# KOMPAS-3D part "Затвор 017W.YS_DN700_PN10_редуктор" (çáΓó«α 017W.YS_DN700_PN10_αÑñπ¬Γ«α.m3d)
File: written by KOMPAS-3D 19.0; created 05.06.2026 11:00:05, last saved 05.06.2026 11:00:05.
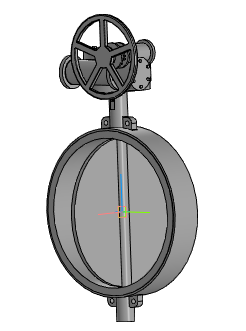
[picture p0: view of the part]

Document properties: Автор: Энергия; Полное имя файла: ..\..\..\3d для проектировщиков\x.x Тип 017W.Y(S) Затвор дисковый поворотный межфланцевый\Затвор 017W.Y(S)_DN50-DN1200_редуктор\Затвор 017W.YS_DN700_PN10_редуктор.a3d

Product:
- Part/product: Затвор 017W.YS_DN700_PN10_редуктор
    Масса: 392.644

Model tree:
1. Операция без истории:1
